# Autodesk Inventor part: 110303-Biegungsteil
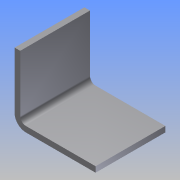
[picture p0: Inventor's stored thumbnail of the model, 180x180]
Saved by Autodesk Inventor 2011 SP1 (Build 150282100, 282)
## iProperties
Created: 2011-03
Part Number: 110303-Biegungsteil
Document SubType Name: Blech
Designer: MP
Mass: 20 g
Surface Area: 112 cm^2
Volume: 20 cm^3
Density: 1 g/cm^3
Flat Pattern Width: 5 cm
Flat Pattern Length: 10 cm
Flat Pattern Area: 50 cm^2
Sheet Metal Rule: Standard
Sheet Metal Width: 50,000 mm
Sheet Metal Length: 100,000 mm
Sheet Metal Area: 5000,000 mm^2
Manager: Michael Puschner
Company: Mensch und Maschine Scholle GmbH
Title: Norm.ipt
Author: MP
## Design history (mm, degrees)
sketch "Skizze1"
  geometry: L1 (-50, 25)-(50, 25); L2 (50, 25)-(50, -25); L3 (50, -25)-(-50, -25); L4 (-50, -25)-(-50, 25); L5 (0, 25)-(0, -25); 2 further points
  constraints: 10 end point, 3 midpoint, 2 parallel, 1 horizontal, 1 horizontal alignment, 1 perpendicular, 1 vertical alignment
  dimensions: "d0" = 100 distance of L1.start L1.end; "d1" = 50 distance of L3.end L1.start
extrude "Extrusion1" new body sketch "Skizze1" stored distance "d2" = 4; taper "d3" = 0 deg
feature "Biegungsteil1" dims "d4" = 6, "d5" = 90 deg
node "Volumenkörper1"
feature "Definition1"
other parameters: "Stärke" = 4 (derived), "KFaktor" = 4.4, "Biegeradius" = 4 (= Stärke), "BreiteBiegungsfreistellung" = 4 (= Stärke), "TiefeBiegungsfreistellung" = 2 (= 0.5 x Stärke), "GrößeEckenfreistellung" = 16 (= 4 x Stärke), "AbstandVerbindung" = 0.01, "MinimalRest" = 8 (= 2 x Stärke), "Übergangsradius" = 4 (= Biegeradius), "JacobiRadiusGröße" = 4 (= Biegeradius), "Abstandsgröße" = 4 (= Stärke), "Abstandsgröße" = 4, "Biegeradius" = 4, "BreiteBiegungsfreistellung" = 4, "GrößeEckenfreistellung" = 16, "JacobiRadiusGröße" = 4, "MinimalRest" = 8, "Stärke" = 4, "TiefeBiegungsfreistellung" = 2, "Übergangsradius" = 4
